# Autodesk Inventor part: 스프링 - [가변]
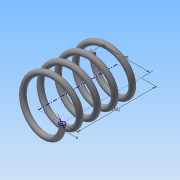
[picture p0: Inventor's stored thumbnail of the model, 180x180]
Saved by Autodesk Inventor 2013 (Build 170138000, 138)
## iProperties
Created: 2015-03
Part Number: 스프링 - [가변]
Material: 강철, 탄소
Document SubType Name: Modeling
Designer: Administrator
Density: 7.87 g/cm^3
Mass: 47.9935 g
Surface Area: 62.0176 cm^2
Volume: 6.09829 cm^3
Author: Administrator
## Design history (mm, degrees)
sketch "스케치1"
  geometry: L1 (0, 0)-(17.5, 0); L2 (17.5, 0)-(17.5, 43.5); L3 (17.5, 43.5)-(0, 43.5); L4 (0, 43.5)-(0, 0); C1 r 2 at (17.5, 0)
  constraints: 8 end point, 2 parallel, 1 centre point, 1 coincident, 1 horizontal, 1 perpendicular
  dimensions: "d0" = 35 diameter of L2 L4; "d2" = 43.5 distance of L1.end L2.end (derived); "d3" = 4 diameter of C1
feature "코일1" sketch "스케치1" pitch "d4" = 10; turns "d6" = 4.5; dims "d5" = 43.5 (= d2), "d7" = 0, angle "d8" = 90 deg, angle "d9" = 90 deg, "d10" = 0, "d11" = 0
sketch "스케치2"
  geometry: L1 (-19.5, 0)-(-15.5, 0) reference; 1 further point
  constraints: 1 horizontal alignment
extrude "돌출1" cut sketch "스케치2" stored distance "d12" = 10; taper "d13" = 0 deg
node "작업 평면1"
sketch "스케치3"
  geometry: L1 (15.5, 0)-(19.5, 0) reference; 1 further point
  constraints: 1 horizontal alignment
extrude "돌출2" cut sketch "스케치3" stored distance "d15" = 10; taper "d16" = 0 deg
node "솔리드1"
node "절단 모서리 투영1"
node "절단 모서리 투영2"
other parameters: "d14" = 43.5 (= d2)
